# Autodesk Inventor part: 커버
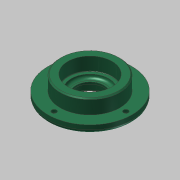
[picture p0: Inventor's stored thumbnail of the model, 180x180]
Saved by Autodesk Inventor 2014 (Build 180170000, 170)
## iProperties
Company: 한국ATC센터
Created: 2016-04
Part Number: 커버
Document SubType Name: Modeling
Designer: mdu
Density: 7.86 g/cm^3
Mass: 351.567 g
Surface Area: 161.165 cm^2
Volume: 44.7286 cm^3
Material: 강철, 연강
Appearance: Steel
Author: mdu
Revision Number: 1
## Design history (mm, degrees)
sketch "스케치1"
  geometry: C1 r 38 at (0, 0); 1 further point
  constraints: 1 centre point, 1 coincident
  dimensions: "d0" = 76 diameter of C1
extrude "돌출1" new body sketch "스케치1" distance "d1" = 7; taper "d2" = 0 deg
sketch "스케치2"
  geometry: C1 r 27 at (0, 0); 1 further point
  constraints: 1 centre point, 1 coincident
  dimensions: "d3" = 54 diameter of C1
extrude "돌출2" join sketch "스케치2" distance "d4" = 13; taper "d5" = 0 deg
sketch "스케치3"
  geometry: C1 r 20 at (0, 0); 1 further point
  constraints: 1 centre point, 1 coincident
  dimensions: "d6" = 40 diameter of C1
extrude "돌출3" join sketch "스케치3" distance "d7" = 5; taper "d8" = 0 deg
hole "구멍1" diameter "d11" = 25; stored, may be unused: countersink angle "d15" = 90 deg, drill point angle "d17" = 118 deg; dims "d9" = 10, "d10" = 10, "d12" = 6, "d13" = 32, "d14" = 8.3, "d16" = 8
hole "구멍2" diameter "d20" = 34; stored, may be unused: countersink angle "d24" = 90 deg, drill point angle "d26" = 0 deg; dims "d18" = 10, "d19" = 10, "d21" = 6, "d22" = 40, "d23" = 12, "d25" = 3
fillet "모깎기2" dims "d34" = 3
fillet "모깎기1" dims "d27" = 0.3
chamfer "모따기1" distance "d28" = 1; stored, may be unused: second distance "d29" = 2, angle "d30" = 45 deg
chamfer "모따기2" distance "d31" = 1.2; stored, may be unused: second distance "d32" = 2, angle "d33" = 30 deg
sketch "스케치4" dims "d35" = 65
  geometry: 3 further points
  constraints: 2 horizontal alignment, 1 coincident, 2 other
hole "구멍3" sketch "스케치4" at (32.5, 0) diameter "d36" = 4.5; stored, may be unused: countersink angle "d40" = 90 deg, drill point angle "d42" = 118 deg; dims "d37" = 6, "d38" = 8, "d39" = 4.4, "d41" = 13
node "솔리드1"
pattern_circular "원형 패턴1" dims angle "d44" = 360 deg
